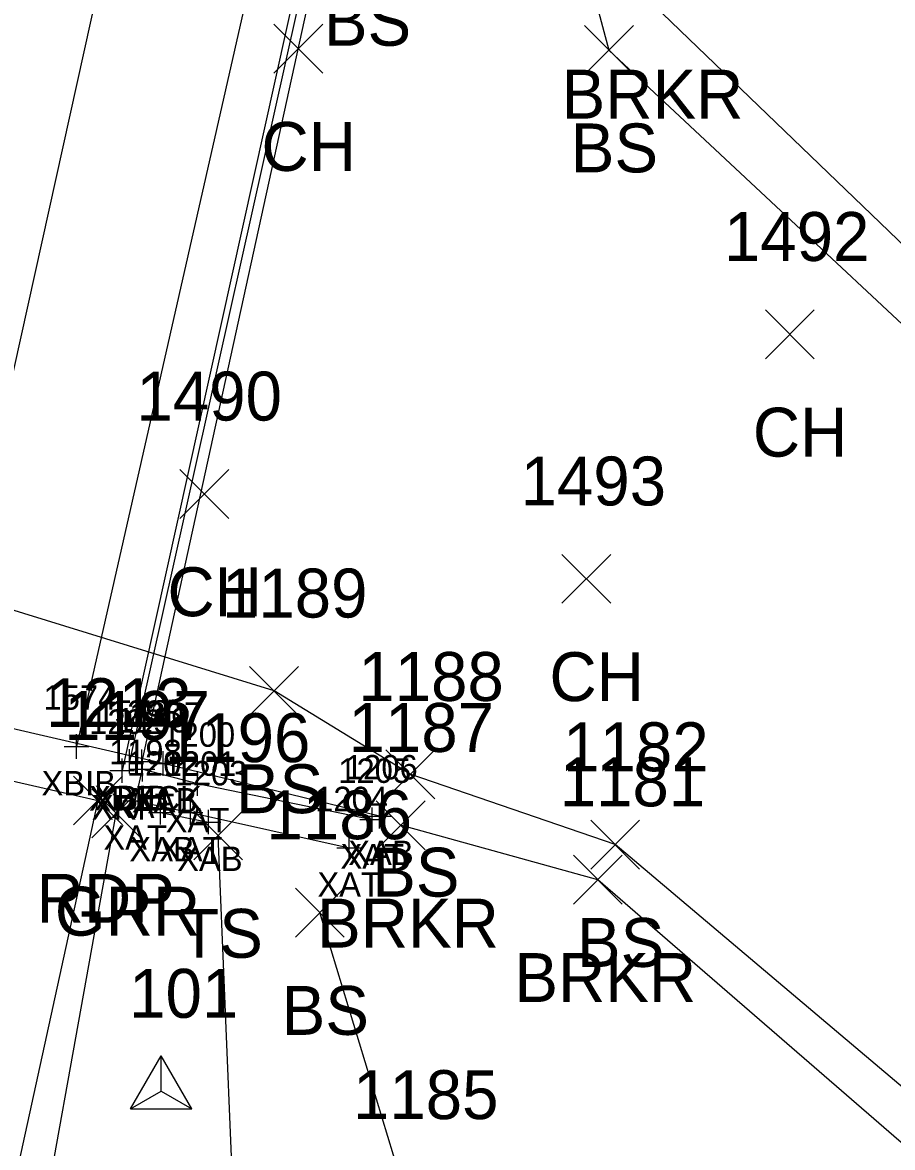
# Model space of a CAD drawing. Extents: x 1654425 to 1656893, y 667839 to 678429.
# Drawn here: x 1654608.79 to 1654644.35, y 668323.56 to 668369.56 of the extents above; entities that cross this region are included whole.
import ezdxf

# ---------------------------------------------------------------- set-up
doc = ezdxf.new("R2010")
doc.units = 0
for name, color, linetype in [('B_A', 7, 'Continuous'), ('B_I', 7, 'Continuous'), ('B_TIC', 7, 'Continuous'), ('BB', 7, 'Continuous'), ('BELB', 7, 'Continuous'), ('BR', 7, 'Continuous'), ('BSUBM', 7, 'Continuous'), ('C_I', 7, 'Continuous'), ('CPSM', 7, 'Continuous'), ('L_A', 7, 'Continuous'), ('L_I', 7, 'Continuous'), ('L_TIC', 7, 'Continuous'), ('LAWE', 7, 'Continuous'), ('LELB', 7, 'Continuous'), ('P_A', 7, 'Continuous'), ('P_I', 7, 'Continuous'), ('P_TIC', 7, 'Continuous'), ('PET', 7, 'Continuous'), ('R_A', 7, 'Continuous'), ('R_I', 7, 'Continuous'), ('R_TIC', 7, 'Continuous'), ('RGR', 7, 'Continuous')]:
    doc.layers.add(name, color=color, linetype=linetype)

msp = doc.modelspace()

# ---------------------------------------------------------------- linework, layer by layer
at = {"layer": 'B_TIC'}
for p, q in [((1654610.997, 668339.958), (1654611.073, 668339.958)), ((1654613.161, 668339.348), (1654613.236, 668339.348)), ((1654613.672, 668339.339), (1654613.748, 668339.339)), ((1654614.544, 668339.26), (1654614.619, 668339.26)), ((1654612.865, 668338.97), (1654612.94, 668338.97)), ((1654613.698, 668339.028), (1654613.773, 668339.028)), ((1654615.94, 668338.443), (1654616.015, 668338.443)), ((1654613.392, 668337.732), (1654613.468, 668337.732)), ((1654613.392, 668337.732), (1654613.468, 668337.732)), ((1654614.439, 668337.262), (1654614.514, 668337.262)), ((1654615.665, 668337.256), (1654615.74, 668337.256)), ((1654616.393, 668336.865), (1654616.469, 668336.865)), ((1654623.087, 668336.967), (1654623.163, 668336.967)), ((1654623.386, 668337.108), (1654623.462, 668337.108)), ((1654622.142, 668335.811), (1654622.217, 668335.811))]:
    msp.add_line(p, q, dxfattribs=at)
for points in [[(1654610.994, 668339.458), (1654610.994, 668340.458)], [(1654610.494, 668339.958), (1654611.494, 668339.958)], [(1654613.157, 668338.848), (1654613.157, 668339.848)], [(1654613.669, 668338.839), (1654613.669, 668339.839)], [(1654614.54, 668338.76), (1654614.54, 668339.76)], [(1654612.657, 668339.348), (1654613.657, 668339.348)], [(1654612.861, 668338.47), (1654612.861, 668339.47)], [(1654613.169, 668339.339), (1654614.169, 668339.339)], [(1654613.694, 668338.528), (1654613.694, 668339.528)], [(1654614.04, 668339.26), (1654615.04, 668339.26)], [(1654612.361, 668338.97), (1654613.361, 668338.97)], [(1654613.194, 668339.028), (1654614.194, 668339.028)], [(1654615.936, 668337.943), (1654615.936, 668338.943)], [(1654613.389, 668337.232), (1654613.389, 668338.232)], [(1654613.389, 668337.232), (1654613.389, 668338.232)], [(1654615.436, 668338.443), (1654616.436, 668338.443)], [(1654614.435, 668336.762), (1654614.435, 668337.762)], [(1654615.661, 668336.756), (1654615.661, 668337.756)], [(1654612.889, 668337.732), (1654613.889, 668337.732)], [(1654612.889, 668337.732), (1654613.889, 668337.732)], [(1654616.39, 668336.365), (1654616.39, 668337.365)], [(1654623.084, 668336.467), (1654623.084, 668337.467)], [(1654623.383, 668336.608), (1654623.383, 668337.608)], [(1654613.935, 668337.262), (1654614.935, 668337.262)], [(1654615.161, 668337.256), (1654616.161, 668337.256)], [(1654615.89, 668336.865), (1654616.89, 668336.865)], [(1654622.584, 668336.967), (1654623.584, 668336.967)], [(1654622.883, 668337.108), (1654623.883, 668337.108)], [(1654622.139, 668335.311), (1654622.139, 668336.311)], [(1654621.639, 668335.811), (1654622.639, 668335.811)]]:
    msp.add_lwpolyline(points, dxfattribs=at)
at = {"layer": 'BB'}
for points in [[(1654613.84, 668379.897), (1654605.3, 668341.294)], [(1654619.73, 668378.476), (1654610.994, 668339.958)], [(1654621.817, 668378.172), (1654613.157, 668339.348)]]:
    msp.add_lwpolyline(points, dxfattribs=at)
at = {"layer": 'BELB'}
msp.add_lwpolyline([(1654622.49, 668379.621), (1654613.669, 668339.339)], dxfattribs=at)
at = {"layer": 'BR'}
msp.add_lwpolyline([(1654621.828, 668379.483), (1654612.861, 668338.97)], dxfattribs=at)
at = {"layer": 'BSUBM'}
for points in [[(1654623.383, 668337.108), (1654614.54, 668339.26), (1654577.279, 668347.876), (1654569.056, 668345.32)], [(1654613.389, 668337.732), (1654613.694, 668339.028), (1654615.936, 668338.443), (1654623.084, 668336.967)], [(1654613.389, 668337.732), (1654615.661, 668337.256), (1654622.139, 668335.811)], [(1654614.435, 668337.262), (1654616.39, 668336.865)]]:
    msp.add_lwpolyline(points, dxfattribs=at)
at = {"layer": 'CPSM'}
for p, q in [((1654613.206, 668325.141), (1654614.456, 668327.306)), ((1654615.706, 668325.141), (1654614.456, 668327.306)), ((1654614.456, 668325.863), (1654614.456, 668327.306)), ((1654613.206, 668325.141), (1654614.456, 668325.863)), ((1654614.456, 668325.863), (1654614.456, 668325.863)), ((1654614.456, 668325.863), (1654615.706, 668325.141)), ((1654613.206, 668325.141), (1654615.706, 668325.141))]:
    msp.add_line(p, q, dxfattribs=at)
at = {"layer": 'L_TIC'}
for points in [[(1654619.069, 668367.489), (1654621.069, 668369.489)], [(1654621.069, 668367.489), (1654619.069, 668369.489)], [(1654631.762, 668367.429), (1654633.762, 668369.429)], [(1654633.762, 668367.429), (1654631.762, 668369.429)], [(1654639.157, 668355.808), (1654641.157, 668357.808)], [(1654641.157, 668355.808), (1654639.157, 668357.808)], [(1654615.226, 668349.283), (1654617.226, 668351.283)], [(1654617.226, 668349.283), (1654615.226, 668351.283)], [(1654630.842, 668345.811), (1654632.842, 668347.811)], [(1654632.842, 668345.811), (1654630.842, 668347.811)], [(1654618.074, 668341.229), (1654620.074, 668343.229)], [(1654620.074, 668341.229), (1654618.074, 668343.229)], [(1654623.642, 668337.818), (1654625.642, 668339.818)], [(1654625.642, 668337.818), (1654623.642, 668339.818)], [(1654615.787, 668335.317), (1654617.787, 668337.317)], [(1654617.787, 668335.317), (1654615.787, 668337.317)], [(1654623.243, 668335.734), (1654625.243, 668337.734)], [(1654625.243, 668335.734), (1654623.243, 668337.734)], [(1654632.016, 668334.944), (1654634.016, 668336.944)], [(1654634.016, 668334.944), (1654632.016, 668336.944)], [(1654631.308, 668333.509), (1654633.308, 668335.509)], [(1654633.308, 668333.509), (1654631.308, 668335.509)], [(1654619.943, 668332.166), (1654621.943, 668334.166)], [(1654621.943, 668332.166), (1654619.943, 668334.166)]]:
    msp.add_lwpolyline(points, dxfattribs=at)
at = {"layer": 'LAWE'}
for points in [[(1654631.343, 668375.967), (1654634.237, 668370.627), (1654654.18, 668351.428), (1654667.189, 668335.715), (1654677.373, 668331.395), (1654692.781, 668302.032), (1654709.543, 668299.626), (1654735.361, 668274.969), (1654748.606, 668254.757), (1654749.341, 668220.043)], [(1654714.238, 668210.789), (1654713.297, 668238.519), (1654709.044, 668250.877), (1654694.772, 668259.682), (1654670.882, 668282.129), (1654651.528, 668317.869), (1654632.308, 668334.509), (1654624.243, 668336.734)]]:
    msp.add_lwpolyline(points, dxfattribs=at)
at = {"layer": 'LELB'}
for points in [[(1654630.798, 668375.77), (1654632.762, 668368.429), (1654652.827, 668349.673), (1654666.039, 668333.882), (1654675.855, 668329.864), (1654689.625, 668301.721), (1654695.034, 668296.343), (1654705.384, 668294.706), (1654731.22, 668271.261), (1654745.828, 668253.452), (1654745.573, 668220.627)], [(1654719.24, 668210.515), (1654718.555, 668239.52), (1654712.255, 668254.013), (1654698.506, 668263.449), (1654673.529, 668283.647), (1654654.274, 668317.984), (1654633.016, 668335.944), (1654624.642, 668338.818), (1654619.074, 668342.229), (1654579.054, 668354.593), (1654565.493, 668358.448), (1654562.652, 668358.715), (1654535.401, 668369.353)], [(1654532.878, 667846.442), (1654536.808, 667893.309), (1654541.082, 667931.047), (1654546.182, 667972.486), (1654551.952, 668011.906), (1654556.54, 668041.437), (1654561.501, 668072.495), (1654571.107, 668129.176), (1654578.927, 668172.429), (1654586.944, 668211.681), (1654595.673, 668254.345), (1654607.408, 668286.917), (1654610.928, 668292.609), (1654617.543, 668318.118), (1654616.787, 668336.317)], [(1654590.306, 668144.878), (1654595.348, 668170.767), (1654599.702, 668209.073), (1654610.676, 668256.645), (1654619.604, 668293.685), (1654624.422, 668321.721), (1654620.943, 668333.166)]]:
    msp.add_lwpolyline(points, dxfattribs=at)
at = {"layer": 'P_TIC'}
for points in [[(1654610.878, 668336.748), (1654612.878, 668338.748)], [(1654612.878, 668336.748), (1654610.878, 668338.748)], [(1654610.878, 668336.748), (1654612.878, 668338.748)], [(1654612.878, 668336.748), (1654610.878, 668338.748)]]:
    msp.add_lwpolyline(points, dxfattribs=at)
at = {"layer": 'PET'}
for points in [[(1654500.928, 667848.144), (1654504.778, 667896.021), (1654509.674, 667937.816), (1654515.365, 667977.677), (1654521.392, 668016.846), (1654525.991, 668046.3), (1654531.262, 668078.241), (1654541.383, 668136.512), (1654548.541, 668178.153), (1654556.412, 668219.498), (1654564.06, 668264.061), (1654572.069, 668308.079), (1654579.914, 668345.234), (1654595.423, 668341.511), (1654611.878, 668337.748)], [(1654528.987, 667846.472), (1654531.958, 667893.38), (1654537.257, 667931.975), (1654542.41, 667973.086), (1654548.22, 668012.23), (1654553.009, 668041.789), (1654558.545, 668073.688), (1654568.046, 668129.99), (1654575.97, 668172.911), (1654583.211, 668212.306), (1654592.644, 668255.655), (1654604.221, 668302.737), (1654611.878, 668337.748)]]:
    msp.add_lwpolyline(points, dxfattribs=at)
at = {"layer": 'R_TIC'}
for points in [[(1654611.622, 668336.222), (1654613.622, 668338.222)], [(1654613.622, 668336.222), (1654611.622, 668338.222)]]:
    msp.add_lwpolyline(points, dxfattribs=at)
at = {"layer": 'RGR'}
msp.add_lwpolyline([(1654609.985, 668283.912), (1654607.408, 668286.917), (1654605.569, 668291.766), (1654605.452, 668297.42), (1654612.622, 668337.222)], dxfattribs=at)

# ---------------------------------------------------------------- texts
at = {"layer": 'B_A'}
for s, p in [('XBIB', (1654609.565, 668337.958)), ('XDECK', (1654611.512, 668337.339)), ('XBIB', (1654611.728, 668337.348)), ('XAB', (1654613.261, 668337.26)), ('XRF', (1654611.621, 668336.97)), ('XAT', (1654612.399, 668337.028)), ('XAT', (1654614.641, 668336.443)), ('XAT', (1654612.094, 668335.732)), ('XAT', (1654612.094, 668335.732)), ('XAB', (1654613.156, 668335.262)), ('XAT', (1654614.366, 668335.256)), ('XAT', (1654621.789, 668334.967)), ('XAB', (1654622.103, 668335.108)), ('XAB', (1654615.11, 668334.865)), ('XAT', (1654620.843, 668333.811))]:
    msp.add_text(s, height=1, dxfattribs=at).set_placement(p)
at = {"layer": 'B_I'}
for s, p in [('1574', (1654609.648, 668341.458)), ('1292', (1654611.515, 668340.47)), ('1573', (1654611.811, 668340.848)), ('1293', (1654612.323, 668340.839)), ('1199', (1654612.627, 668340.528)), ('1207', (1654613.155, 668340.76)), ('1200', (1654614.507, 668339.943)), ('1198', (1654612.326, 668339.232)), ('1198', (1654612.326, 668339.232)), ('1202', (1654613.05, 668338.762)), ('1201', (1654614.559, 668338.756)), ('1206', (1654621.969, 668338.608)), ('1203', (1654615.004, 668338.365)), ('1205', (1654621.698, 668338.467)), ('1204', (1654620.753, 668337.311))]:
    msp.add_text(s, height=1, dxfattribs=at).set_placement(p)
at = {"layer": 'C_I'}
msp.add_text('101', height=2, dxfattribs=at).set_placement((1654613.149, 668328.863))
at = {"layer": 'L_A'}
for s, p in [('BS', (1654621.109, 668368.608)), ('BRKR', (1654630.827, 668365.627)), ('CH', (1654618.557, 668363.489)), ('BS', (1654631.203, 668363.429)), ('CH', (1654638.645, 668351.808)), ('CH', (1654614.714, 668345.283)), ('CH', (1654630.33, 668341.811)), ('BS', (1654617.515, 668337.229)), ('BS', (1654623.083, 668333.818)), ('BRKR', (1654620.833, 668331.734)), ('TS', (1654615.197, 668331.317)), ('BS', (1654631.457, 668330.944)), ('BRKR', (1654628.898, 668329.509)), ('BS', (1654619.384, 668328.166))]:
    msp.add_text(s, height=2, dxfattribs=at).set_placement(p)
at = {"layer": 'L_I'}
for s, p in [('1492', (1654637.464, 668359.808)), ('1490', (1654613.446, 668353.283)), ('1493', (1654629.149, 668349.811)), ('1189', (1654616.941, 668345.229)), ('1188', (1654622.516, 668341.818)), ('1187', (1654622.117, 668339.734)), ('1196', (1654614.607, 668339.317)), ('1182', (1654630.891, 668338.944)), ('1181', (1654630.749, 668337.509)), ('1186', (1654618.762, 668336.166)), ('1185', (1654622.297, 668324.721))]:
    msp.add_text(s, height=2, dxfattribs=at).set_placement(p)
at = {"layer": 'P_A'}
msp.add_text('RDP', height=2, dxfattribs=at).set_placement((1654609.366, 668332.748))
msp.add_text('RDP', height=2, dxfattribs=at).set_placement((1654609.366, 668332.748))
at = {"layer": 'P_I'}
msp.add_text('1213', height=2, dxfattribs=at).set_placement((1654609.752, 668340.748))
msp.add_text('1213', height=2, dxfattribs=at).set_placement((1654609.752, 668340.748))
at = {"layer": 'R_A'}
msp.add_text('GRR', height=2, dxfattribs=at).set_placement((1654610.11, 668332.222))
at = {"layer": 'R_I'}
msp.add_text('1197', height=2, dxfattribs=at).set_placement((1654610.497, 668340.222))

doc.saveas('drawing.dxf')
